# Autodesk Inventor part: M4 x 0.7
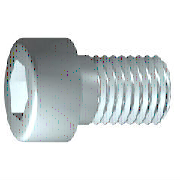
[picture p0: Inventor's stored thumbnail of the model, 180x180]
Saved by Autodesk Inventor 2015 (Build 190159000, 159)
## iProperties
IsCustomPart: 0
Created: 2015-10
Part Number: M4 x 0.7
Material: 강, 연강
Description: 6각머리 태핑 나사
Document SubType Name: Modeling
Standard: KS B 1003
Designer: mdu
Standards Organization: KS
Language: ko-KR
Size Designation: M 4 x 25
Categories: <MemberInstance><Categories><Category DisplayName="조임쇠" InternalName="e4da775c-781d-43d5-af7c-5136215cf5a6" Mnemonic="FSTN"><Category DisplayName="볼트" InternalN
Density: 1 g/cm^3
Appearance: 강철
Author: mdu
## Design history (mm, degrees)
sketch "스케치1"
  geometry: L1 (-1, 0)-(25, 0); L2 (25, 0)-(25, 2); L3 (25, 2)-(1.75, 2); L4 (1.75, 2)-(1.32, 2); L5 (1.32, 2)-(0, 2); L6 (0, 2)-(0, 3.5); L7 (0, 3.5)-(-4, 3.5); L8 (-4, 3.5)-(-4, 1.732); L9 (-4, 1.732)-(-2, 1.732); L10 (-2, 1.732)-(-1, 0); L11 (-9.8, 0)-(30.8, 0) reference; L12 (0, -0.7)-(0, 4.2) reference; L13 (1.75, 2)-(0, 2)
  constraints: 22 end point, 6 parallel, 2 collinear, 2 perpendicular, 1 horizontal, 1 point on line
  dimensions: "d1" = 23.25 distance from line of L3.end L2 (= GEL); "d2" = 0.42952 distance of L4.end L3.end (computed from GAL); "d3" = 4 distance between parallel lines of L8 L6 (= KOH); "d4" = 2 distance of L8.end L9.end (= INTI); "d5" = 60 deg angle of L10 L1; "d6" = 4 diameter of L3 L1 (= GD); "d7" = 4 diameter of L5 L1 (= BDM); "d8" = 3.4641 diameter of L9 L1 (= 1.1547 x SW); "d9" = 7 diameter of L7 L1 (= KOD); "d26" = 25 distance between parallel lines of L12 L2 (= NLG)
revolve "본체" sketch "스케치1" stored, may be unused: angle "d10" = 90 deg
sketch "스케치2"
  geometry: L1 (0, -4.9)-(0, 4.9) reference; L2 (-4.9, 0)-(4.9, 0) reference; L3 (1.732, 0)-(0.866, -1.5); L4 (0.866, -1.5)-(-0.866, -1.5); L5 (-0.866, -1.5)-(-1.732, 0); L6 (-1.732, 0)-(-0.866, 1.5); L7 (-0.866, 1.5)-(0.866, 1.5); L8 (0.866, 1.5)-(1.732, 0); 2 further points
  constraints: 12 end point, 1 coincident, 1 horizontal alignment, 1 point on line, 12 other
extrude "슬롯" join sketch "스케치2" stored distance "d11" = 10; taper "d12" = 0 deg
workplane "Work Plane1"
fillet "Fillet2" dims "d30" = 0.1 (= R)
body "Solid1"
fillet "모깎기1" dims "d17" = 0.4 (= RR)
feature "스레드" dims "d13" = 23.25 (= GEL), "d14" = 0
chamfer "모따기1" distance "d15" = 0.42941 (= -0.5 x SPD + 0.5 x GD); stored, may be unused: second distance "d16" = 0.42941 (= GUL), angle "d27" = 45 deg
other parameters: "GD" = 4 (= NND) [user parameter; used in 2 equation terms], "NLG" = 25 [user parameter; used in 1 equation term], "GEL" = 23.25 [user parameter; used in 2 equation terms], "KOD" = 7 [user parameter; used in 1 equation term], "KOH" = 4 [user parameter; used in 1 equation term], "INTI" = 2 [user parameter; used in 1 equation term], "GAL" = 0.42941 (= 0.61345 x PTC) [user parameter; used in 1 equation term], "GUL" = 0.42941 (= 0.61345 x PTC) [user parameter; used in 1 equation term], "BDM" = 4 (= NND) [user parameter; used in 1 equation term], "SW" = 3 [user parameter; used in 2 equation terms], "RR" = 0.4 [user parameter; used in 1 equation term], "SPD" = 3.14117 (= NND - 1.2269 x PTC) [user parameter; used in 1 equation term], "d19" = 0, "d28" = 0, "d29" = 0, "R" = 0.1 [user parameter; used in 1 equation term], "PHH" = 0.2 [user parameter], "GD1" = 3.14117 (= THREADDIA - 1.2269 x PTC) [user parameter], "THREADDIA" = 4 [user parameter; used in 1 equation term], "FAWI" = 45 deg [user parameter], "TPU" = 14.28571 (computed from PTC) [user parameter], "PTC" = 0.7 [user parameter; used in 5 equation terms], "NND" = 4 [user parameter; used in 3 equation terms], "TOA" = 30 deg [user parameter], "E0" = 3.465 (= 1.155 x SW) [user parameter]
